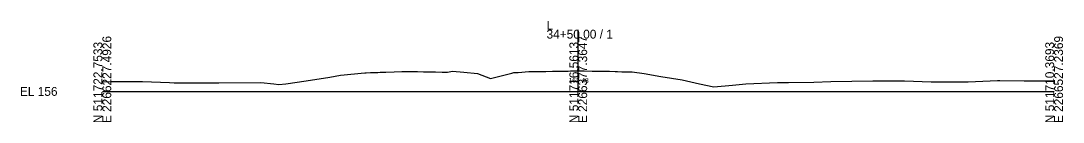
# Model space of a CAD drawing. Extents: x -827 to 2303, y -169 to 9934.
# Drawn here: x 1974.3 to 2302.8, y 3490.3 to 3522.2 of the extents above; entities that cross this region are included whole.
import ezdxf

# ---------------------------------------------------------------- set-up
doc = ezdxf.new("R2010")
doc.units = 0
for name, color, linetype in [('Default', 7, 'Continuous'), ('Exist Cross Section Cell', 7, 'Continuous'), ('Exist XS Center Line Elevation Label', 7, 'Continuous'), ('Exist XS Ground Line', 7, 'Continuous')]:
    doc.layers.add(name, color=color, linetype=linetype)

msp = doc.modelspace()

# ---------------------------------------------------------------- linework, layer by layer
at = {"layer": 'Exist Cross Section Cell'}
for p, q in [((2150, 3500), (2150, 3519.44)), ((2000, 3500), (2150, 3500)), ((2150, 3500), (2300, 3500))]:
    msp.add_line(p, q, dxfattribs=at)
at = {"layer": 'Exist XS Ground Line'}
msp.add_lwpolyline([(2000, 3503.03), (2002.59, 3503.07), (2010.7, 3503.1), (2012.6, 3503.1), (2021.14, 3502.78), (2022.61, 3502.67), (2031.58, 3502.71), (2032.62, 3502.73), (2036.73, 3502.75), (2049.9, 3502.76), (2054.01, 3502.34), (2055.61, 3502.13), (2057.82, 3502.43), (2064.22, 3503.3), (2071.65, 3504.54), (2075.01, 3505.07), (2076.18, 3505.18), (2081.62, 3505.71), (2082.76, 3505.85), (2083.19, 3505.89), (2084.48, 3505.94), (2086.85, 3506), (2087.58, 3506.03), (2089.34, 3506.11), (2092.01, 3506.17), (2094.44, 3506.26), (2095.18, 3506.28), (2096.5, 3506.28), (2096.83, 3506.28), (2097.24, 3506.27), (2099.32, 3506.24), (2101.23, 3506.21), (2101.81, 3506.2), (2103.64, 3506.16), (2104.31, 3506.15), (2105.04, 3506.14), (2107.08, 3506.11), (2107.69, 3506.1), (2108.79, 3506.09), (2110.4, 3506.33), (2113.93, 3506.02), (2118.23, 3505.64), (2122.34, 3504.07), (2129.08, 3505.8), (2129.66, 3505.91), (2131.07, 3506.01), (2134.47, 3506.3), (2135.88, 3506.26), (2136.74, 3506.25), (2137.19, 3506.25), (2137.75, 3506.25), (2138.96, 3506.28), (2139.39, 3506.29), (2139.73, 3506.3), (2141.89, 3506.34), (2144.37, 3506.39), (2146.87, 3506.43), (2147.6, 3506.44), (2149.4, 3506.47), (2150.16, 3506.48), (2151.85, 3506.45), (2154.35, 3506.42), (2156.49, 3506.39), (2156.85, 3506.38), (2158.92, 3506.35), (2159.37, 3506.34), (2159.81, 3506.34), (2161.65, 3506.32), (2162.33, 3506.29), (2163.73, 3506.19), (2166.99, 3506.14), (2170.82, 3505.66), (2176.01, 3504.72), (2182.76, 3503.63), (2188.2, 3502.36), (2192.77, 3501.44), (2198.64, 3501.93), (2202.78, 3502.38), (2212.85, 3502.77), (2213.41, 3502.78), (2216.22, 3502.81), (2224.22, 3502.95), (2229.59, 3503.08), (2242.82, 3503.37), (2250.84, 3503.34), (2252.83, 3503.34), (2261.28, 3503.03), (2262.84, 3503.06), (2271.73, 3503.02), (2272.85, 3503.04), (2282.17, 3503.4), (2282.86, 3503.39), (2290.59, 3503.28), (2293.15, 3503.34), (2300, 3503.37)], dxfattribs=at)

# ---------------------------------------------------------------- texts
at = {"layer": 'Default'}
msp.add_text('-', height=0.0001, dxfattribs=at).set_placement((2000, 3500))
msp.add_text('-', height=0.0001, dxfattribs=at).set_placement((2000, 3500))
at = {"layer": 'Exist Cross Section Cell'}
for s, p in [('L', (2140, 3519.44)), ('34+50.00 / 1', (2140, 3516.64)), ('EL 156', (1974, 3498.6))]:
    msp.add_text(s, height=2.8, dxfattribs=at).set_placement(p)
for s, p in [('N 511722.7533', (2000, 3490)), ('E 2266227.4926', (2002.8, 3490)), ('N 511716.5613', (2150, 3490)), ('E 2266377.3647', (2152.8, 3490)), ('N 511710.3693', (2300, 3490)), ('E 2266527.2369', (2302.8, 3490))]:
    msp.add_text(s, height=2.8, rotation=90, dxfattribs=at).set_placement(p)
at = {"layer": 'Exist XS Center Line Elevation Label'}
msp.add_text('162.48', height=1.5, dxfattribs=at).set_placement((2146.96, 3502.73))

doc.saveas('drawing.dxf')
